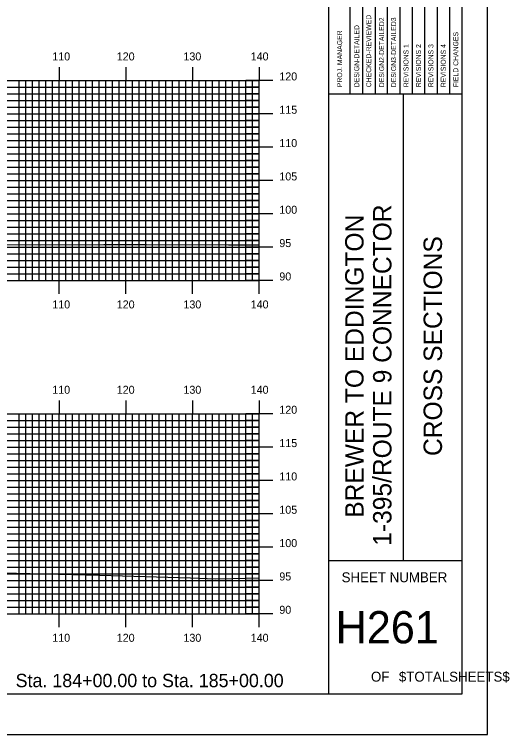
# Model space of a CAD drawing. Extents: x 1786976 to 1787319, y 442591 to 442811.
# Drawn here: x 1787244.9 to 1787319.1, y 442590.5 to 442698.6 of the extents above; entities that cross this region are included whole.
import ezdxf

# ---------------------------------------------------------------- set-up
doc = ezdxf.new("R2010")
doc.units = 0
for name, color, linetype in [('BORDER', 7, 'Continuous'), ('H_V ANNOTATION', 7, 'Continuous'), ('MAJOR', 7, 'Continuous'), ('MINOR', 7, 'Continuous'), ('PLOT BOUNDARY', 7, 'Continuous'), ('S_Roadway_Centerline', 7, 'Continuous')]:
    doc.layers.add(name, color=color, linetype=linetype)

msp = doc.modelspace()

# ---------------------------------------------------------------- linework, layer by layer
at = {"layer": 'BORDER'}
for p, q in [((1787291.99, 442596.67), (1787291.99, 442806.67)), ((1787291.99, 442686.67), (1787311.99, 442686.67)), ((1787303.17, 442616.67), (1787303.17, 442686.67)), ((1787291.99, 442616.67), (1787311.99, 442616.67))]:
    msp.add_line(p, q, dxfattribs=at)
msp.add_lwpolyline([(1786991.99, 442596.67), (1787311.99, 442596.67), (1787311.99, 442806.67), (1786991.99, 442806.67)], close=True, dxfattribs=at)
for points in [[(1787297.09, 442686.68), (1787297.09, 442721.67)], [(1787298.95, 442721.67), (1787298.95, 442686.68)], [(1787300.81, 442686.68), (1787300.81, 442721.67)], [(1787302.68, 442686.68), (1787302.68, 442721.67)], [(1787304.54, 442686.68), (1787304.54, 442721.67)], [(1787306.4, 442686.68), (1787306.4, 442721.67)], [(1787308.27, 442686.68), (1787308.27, 442721.67)], [(1787310.13, 442686.68), (1787310.13, 442721.67)], [(1787295.22, 442686.68), (1787295.22, 442720.26)]]:
    msp.add_lwpolyline(points, dxfattribs=at)
at = {"layer": 'MAJOR'}
for p, q in [((1787251.59, 442690.67), (1787251.59, 442688.67)), ((1787261.59, 442690.67), (1787261.59, 442688.67)), ((1787271.59, 442690.67), (1787271.59, 442688.67)), ((1787281.59, 442690.67), (1787281.59, 442688.67)), ((1787001.59, 442688.67), (1787281.59, 442688.67)), ((1787001.59, 442688.67), (1787281.59, 442688.67)), ((1787251.59, 442658.67), (1787251.59, 442688.67)), ((1787261.59, 442658.67), (1787261.59, 442688.67)), ((1787271.59, 442658.67), (1787271.59, 442688.67)), ((1787283.6, 442688.67), (1787279.59, 442688.67)), ((1787281.59, 442658.67), (1787281.59, 442688.67)), ((1787281.59, 442658.67), (1787281.59, 442688.67)), ((1787001.59, 442683.67), (1787281.59, 442683.67)), ((1787283.6, 442683.67), (1787279.59, 442683.67)), ((1787001.59, 442678.67), (1787281.59, 442678.67)), ((1787283.6, 442678.67), (1787279.59, 442678.67)), ((1787001.59, 442673.67), (1787281.59, 442673.67)), ((1787283.6, 442673.67), (1787279.59, 442673.67)), ((1787001.59, 442668.67), (1787281.59, 442668.67)), ((1787283.6, 442668.67), (1787279.59, 442668.67)), ((1787001.59, 442663.67), (1787281.59, 442663.67)), ((1787283.6, 442663.67), (1787279.59, 442663.67)), ((1787001.59, 442658.67), (1787281.59, 442658.67)), ((1787001.59, 442658.67), (1787281.59, 442658.67)), ((1787251.59, 442656.66), (1787251.59, 442658.67)), ((1787261.59, 442656.66), (1787261.59, 442658.67)), ((1787271.59, 442656.66), (1787271.59, 442658.67)), ((1787283.6, 442658.67), (1787279.59, 442658.67)), ((1787281.59, 442656.66), (1787281.59, 442658.67)), ((1787251.59, 442640.67), (1787251.59, 442638.67)), ((1787261.59, 442640.67), (1787261.59, 442638.67)), ((1787271.59, 442640.67), (1787271.59, 442638.67)), ((1787281.59, 442640.67), (1787281.59, 442638.67)), ((1787001.59, 442638.67), (1787281.59, 442638.67)), ((1787001.59, 442638.67), (1787281.59, 442638.67)), ((1787251.59, 442608.67), (1787251.59, 442638.67)), ((1787261.59, 442608.67), (1787261.59, 442638.67)), ((1787271.59, 442608.67), (1787271.59, 442638.67)), ((1787283.6, 442638.67), (1787279.59, 442638.67)), ((1787281.59, 442608.67), (1787281.59, 442638.67)), ((1787281.59, 442608.67), (1787281.59, 442638.67)), ((1787001.59, 442633.67), (1787281.59, 442633.67)), ((1787283.6, 442633.67), (1787279.59, 442633.67)), ((1787001.59, 442628.67), (1787281.59, 442628.67)), ((1787283.6, 442628.67), (1787279.59, 442628.67)), ((1787001.59, 442623.67), (1787281.59, 442623.67)), ((1787283.6, 442623.67), (1787279.59, 442623.67)), ((1787001.59, 442618.67), (1787281.59, 442618.67)), ((1787283.6, 442618.67), (1787279.59, 442618.67)), ((1787001.59, 442613.67), (1787281.59, 442613.67)), ((1787283.6, 442613.67), (1787279.59, 442613.67)), ((1787001.59, 442608.67), (1787281.59, 442608.67)), ((1787001.59, 442608.67), (1787281.59, 442608.67)), ((1787251.59, 442606.66), (1787251.59, 442608.67)), ((1787261.59, 442606.66), (1787261.59, 442608.67)), ((1787271.59, 442606.66), (1787271.59, 442608.67)), ((1787283.6, 442608.67), (1787279.59, 442608.67)), ((1787281.59, 442606.66), (1787281.59, 442608.67))]:
    msp.add_line(p, q, dxfattribs=at)
at = {"layer": 'MINOR'}
for p, q in [((1787245.59, 442658.67), (1787245.59, 442688.67)), ((1787246.59, 442658.67), (1787246.59, 442688.67)), ((1787247.59, 442658.67), (1787247.59, 442688.67)), ((1787248.59, 442658.67), (1787248.59, 442688.67)), ((1787249.59, 442658.67), (1787249.59, 442688.67)), ((1787250.59, 442658.67), (1787250.59, 442688.67)), ((1787252.59, 442658.67), (1787252.59, 442688.67)), ((1787253.59, 442658.67), (1787253.59, 442688.67)), ((1787254.59, 442658.67), (1787254.59, 442688.67)), ((1787255.59, 442658.67), (1787255.59, 442688.67)), ((1787256.59, 442658.67), (1787256.59, 442688.67)), ((1787257.59, 442658.67), (1787257.59, 442688.67)), ((1787258.59, 442658.67), (1787258.59, 442688.67)), ((1787259.59, 442658.67), (1787259.59, 442688.67)), ((1787260.59, 442658.67), (1787260.59, 442688.67)), ((1787262.59, 442658.67), (1787262.59, 442688.67)), ((1787263.59, 442658.67), (1787263.59, 442688.67)), ((1787264.59, 442658.67), (1787264.59, 442688.67)), ((1787265.59, 442658.67), (1787265.59, 442688.67)), ((1787266.59, 442658.67), (1787266.59, 442688.67)), ((1787267.59, 442658.67), (1787267.59, 442688.67)), ((1787268.59, 442658.67), (1787268.59, 442688.67)), ((1787269.59, 442658.67), (1787269.59, 442688.67)), ((1787270.59, 442658.67), (1787270.59, 442688.67)), ((1787272.59, 442658.67), (1787272.59, 442688.67)), ((1787273.59, 442658.67), (1787273.59, 442688.67)), ((1787274.59, 442658.67), (1787274.59, 442688.67)), ((1787275.59, 442658.67), (1787275.59, 442688.67)), ((1787276.59, 442658.67), (1787276.59, 442688.67)), ((1787277.59, 442658.67), (1787277.59, 442688.67)), ((1787278.59, 442658.67), (1787278.59, 442688.67)), ((1787279.59, 442658.67), (1787279.59, 442688.67)), ((1787280.59, 442658.67), (1787280.59, 442688.67)), ((1787001.59, 442687.67), (1787281.59, 442687.67)), ((1787281.59, 442687.67), (1787279.59, 442687.67)), ((1787001.59, 442686.67), (1787281.59, 442686.67)), ((1787281.59, 442686.67), (1787279.59, 442686.67)), ((1787001.59, 442685.67), (1787281.59, 442685.67)), ((1787281.59, 442685.67), (1787279.59, 442685.67)), ((1787001.59, 442684.67), (1787281.59, 442684.67)), ((1787281.59, 442684.67), (1787279.59, 442684.67)), ((1787001.59, 442682.67), (1787281.59, 442682.67)), ((1787281.59, 442682.67), (1787279.59, 442682.67)), ((1787001.59, 442681.67), (1787281.59, 442681.67)), ((1787001.59, 442680.67), (1787281.59, 442680.67)), ((1787281.59, 442681.67), (1787279.59, 442681.67)), ((1787281.59, 442680.67), (1787279.59, 442680.67)), ((1787001.59, 442679.67), (1787281.59, 442679.67)), ((1787281.59, 442679.67), (1787279.59, 442679.67)), ((1787001.59, 442677.67), (1787281.59, 442677.67)), ((1787281.59, 442677.67), (1787279.59, 442677.67)), ((1787001.59, 442676.67), (1787281.59, 442676.67)), ((1787281.59, 442676.67), (1787279.59, 442676.67)), ((1787001.59, 442675.67), (1787281.59, 442675.67)), ((1787281.59, 442675.67), (1787279.59, 442675.67)), ((1787001.59, 442674.67), (1787281.59, 442674.67)), ((1787281.59, 442674.67), (1787279.59, 442674.67)), ((1787001.59, 442672.67), (1787281.59, 442672.67)), ((1787281.59, 442672.67), (1787279.59, 442672.67)), ((1787001.59, 442671.67), (1787281.59, 442671.67)), ((1787281.59, 442671.67), (1787279.59, 442671.67)), ((1787001.59, 442670.67), (1787281.59, 442670.67)), ((1787281.59, 442670.67), (1787279.59, 442670.67)), ((1787001.59, 442669.67), (1787281.59, 442669.67)), ((1787281.59, 442669.67), (1787279.59, 442669.67)), ((1787001.59, 442667.67), (1787281.59, 442667.67)), ((1787281.59, 442667.67), (1787279.59, 442667.67)), ((1787001.59, 442666.67), (1787281.59, 442666.67)), ((1787281.59, 442666.67), (1787279.59, 442666.67)), ((1787001.59, 442665.67), (1787281.59, 442665.67)), ((1787281.59, 442665.67), (1787279.59, 442665.67)), ((1787001.59, 442664.67), (1787281.59, 442664.67)), ((1787281.59, 442664.67), (1787279.59, 442664.67)), ((1787001.59, 442662.67), (1787281.59, 442662.67)), ((1787281.59, 442662.67), (1787279.59, 442662.67)), ((1787001.59, 442661.67), (1787281.59, 442661.67)), ((1787281.59, 442661.67), (1787279.59, 442661.67)), ((1787001.59, 442660.67), (1787281.59, 442660.67)), ((1787281.59, 442660.67), (1787279.59, 442660.67)), ((1787001.59, 442659.67), (1787281.59, 442659.67)), ((1787281.59, 442659.67), (1787279.59, 442659.67)), ((1787245.59, 442608.67), (1787245.59, 442638.67)), ((1787246.59, 442608.67), (1787246.59, 442638.67)), ((1787247.59, 442608.67), (1787247.59, 442638.67)), ((1787248.59, 442608.67), (1787248.59, 442638.67)), ((1787249.59, 442608.67), (1787249.59, 442638.67)), ((1787250.59, 442608.67), (1787250.59, 442638.67)), ((1787252.59, 442608.67), (1787252.59, 442638.67)), ((1787253.59, 442608.67), (1787253.59, 442638.67)), ((1787254.59, 442608.67), (1787254.59, 442638.67)), ((1787255.59, 442608.67), (1787255.59, 442638.67)), ((1787256.59, 442608.67), (1787256.59, 442638.67)), ((1787257.59, 442608.67), (1787257.59, 442638.67)), ((1787258.59, 442608.67), (1787258.59, 442638.67)), ((1787259.59, 442608.67), (1787259.59, 442638.67)), ((1787260.59, 442608.67), (1787260.59, 442638.67)), ((1787262.59, 442608.67), (1787262.59, 442638.67)), ((1787263.59, 442608.67), (1787263.59, 442638.67)), ((1787264.59, 442608.67), (1787264.59, 442638.67)), ((1787265.59, 442608.67), (1787265.59, 442638.67)), ((1787266.59, 442608.67), (1787266.59, 442638.67)), ((1787267.59, 442608.67), (1787267.59, 442638.67)), ((1787268.59, 442608.67), (1787268.59, 442638.67)), ((1787269.59, 442608.67), (1787269.59, 442638.67)), ((1787270.59, 442608.67), (1787270.59, 442638.67)), ((1787272.59, 442608.67), (1787272.59, 442638.67)), ((1787273.59, 442608.67), (1787273.59, 442638.67)), ((1787274.59, 442608.67), (1787274.59, 442638.67)), ((1787275.59, 442608.67), (1787275.59, 442638.67)), ((1787276.59, 442608.67), (1787276.59, 442638.67)), ((1787277.59, 442608.67), (1787277.59, 442638.67)), ((1787278.59, 442608.67), (1787278.59, 442638.67)), ((1787279.59, 442608.67), (1787279.59, 442638.67)), ((1787280.59, 442608.67), (1787280.59, 442638.67)), ((1787001.59, 442637.67), (1787281.59, 442637.67)), ((1787281.59, 442637.67), (1787279.59, 442637.67)), ((1787001.59, 442636.67), (1787281.59, 442636.67)), ((1787281.59, 442636.67), (1787279.59, 442636.67)), ((1787001.59, 442635.67), (1787281.59, 442635.67)), ((1787281.59, 442635.67), (1787279.59, 442635.67)), ((1787001.59, 442634.67), (1787281.59, 442634.67)), ((1787281.59, 442634.67), (1787279.59, 442634.67)), ((1787001.59, 442632.67), (1787281.59, 442632.67)), ((1787281.59, 442632.67), (1787279.59, 442632.67)), ((1787001.59, 442631.67), (1787281.59, 442631.67)), ((1787281.59, 442631.67), (1787279.59, 442631.67)), ((1787001.59, 442630.67), (1787281.59, 442630.67)), ((1787281.59, 442630.67), (1787279.59, 442630.67)), ((1787001.59, 442629.67), (1787281.59, 442629.67)), ((1787281.59, 442629.67), (1787279.59, 442629.67)), ((1787001.59, 442627.67), (1787281.59, 442627.67)), ((1787281.59, 442627.67), (1787279.59, 442627.67)), ((1787001.59, 442626.67), (1787281.59, 442626.67)), ((1787281.59, 442626.67), (1787279.59, 442626.67)), ((1787001.59, 442625.67), (1787281.59, 442625.67)), ((1787281.59, 442625.67), (1787279.59, 442625.67)), ((1787001.59, 442624.67), (1787281.59, 442624.67)), ((1787281.59, 442624.67), (1787279.59, 442624.67)), ((1787001.59, 442622.67), (1787281.59, 442622.67)), ((1787281.59, 442622.67), (1787279.59, 442622.67)), ((1787001.59, 442621.67), (1787281.59, 442621.67)), ((1787281.59, 442621.67), (1787279.59, 442621.67)), ((1787001.59, 442620.67), (1787281.59, 442620.67)), ((1787281.59, 442620.67), (1787279.59, 442620.67)), ((1787001.59, 442619.67), (1787281.59, 442619.67)), ((1787281.59, 442619.67), (1787279.59, 442619.67)), ((1787001.59, 442617.67), (1787281.59, 442617.67)), ((1787281.59, 442617.67), (1787279.59, 442617.67)), ((1787001.59, 442616.67), (1787281.59, 442616.67)), ((1787281.59, 442616.67), (1787279.59, 442616.67)), ((1787001.59, 442615.67), (1787281.59, 442615.67)), ((1787281.59, 442615.67), (1787279.59, 442615.67)), ((1787001.59, 442614.67), (1787281.59, 442614.67)), ((1787281.59, 442614.67), (1787279.59, 442614.67)), ((1787001.59, 442612.67), (1787281.59, 442612.67)), ((1787281.59, 442612.67), (1787279.59, 442612.67)), ((1787001.59, 442611.67), (1787281.59, 442611.67)), ((1787281.59, 442611.67), (1787279.59, 442611.67)), ((1787001.59, 442610.67), (1787281.59, 442610.67)), ((1787281.59, 442610.67), (1787279.59, 442610.67)), ((1787001.59, 442609.67), (1787281.59, 442609.67)), ((1787281.59, 442609.67), (1787279.59, 442609.67))]:
    msp.add_line(p, q, dxfattribs=at)
at = {"layer": 'PLOT BOUNDARY'}
msp.add_lwpolyline([(1786975.8, 442590.55), (1787315.8, 442590.55), (1787315.8, 442810.55), (1786975.8, 442810.55)], close=True, dxfattribs=at)
at = {"layer": 'S_Roadway_Centerline'}
for points in [[(1787171.93, 442664.67), (1787182.34, 442664.47), (1787200.72, 442664.18), (1787201.57, 442664.17), (1787202.18, 442664.16), (1787211, 442664.25), (1787218.19, 442664.24), (1787222.27, 442664.23), (1787229.46, 442664.14), (1787242.18, 442664.04), (1787248.78, 442664.02), (1787258.29, 442664.07), (1787262.4, 442664.07), (1787264.7, 442664.07), (1787276.96, 442664.02), (1787281.59, 442664)], [(1787177.27, 442614.71), (1787185.92, 442614.82), (1787196.31, 442614.87), (1787197.54, 442614.84), (1787204.65, 442614.76), (1787214.46, 442614.94), (1787217.7, 442614.94), (1787225.22, 442614.93), (1787237.74, 442614.87), (1787243.12, 442614.8), (1787257.71, 442614.46), (1787271.3, 442614.07), (1787275.05, 442613.91), (1787277.58, 442613.95), (1787281.59, 442614.05)]]:
    msp.add_lwpolyline(points, dxfattribs=at)

# ---------------------------------------------------------------- texts
at = {"layer": 'BORDER'}
for s, height, p in [('CHECKED-REVIEWED', 0.7455, (1787298.35, 442687.65)), ('DESIGN2-DETAILED2', 0.7455, (1787300.29, 442687.65)), ('DESIGN3-DETAILED3', 0.7455, (1787302.08, 442687.65)), ('PROJ. MANAGER', 0.7455, (1787294, 442687.65)), ('DESIGN-DETAILED', 0.7455, (1787296.56, 442687.65)), ('FIELD CHANGES', 0.7455, (1787311.4, 442687.65)), ('REVISIONS 1', 0.7455, (1787303.94, 442687.65)), ('REVISIONS 2', 0.7455, (1787305.81, 442687.65)), ('REVISIONS 3', 0.7455, (1787307.67, 442687.65)), ('REVISIONS 4', 0.7455, (1787309.53, 442687.65)), ('1-395/ROUTE 9 CONNECTOR', 2.7557, (1787301.39, 442618.87)), ('BREWER TO EDDINGTON', 2.7557, (1787297.21, 442623.07)), ('CROSS SECTIONS', 2.7557, (1787308.96, 442632.34))]:
    msp.add_text(s, height=height, rotation=90, dxfattribs=at).set_placement(p)
for s, height, p in [('SHEET NUMBER', 1.4905, (1787293.92, 442613.4)), ('H261', 4.839, (1787293.02, 442604.23)), ('OF', 1.491, (1787298.32, 442598.49)), ('$TOTALSHEETS$', 1.4905, (1787302.5, 442598.49))]:
    msp.add_text(s, height=height, dxfattribs=at).set_placement(p)
at = {"layer": 'H_V ANNOTATION'}
for s, height, p in [('110', 1.2, (1787250.57, 442691.67)), ('120', 1.2, (1787260.23, 442691.67)), ('130', 1.2, (1787270.22, 442691.67)), ('140', 1.2, (1787280.3, 442691.67)), ('120', 1.2, (1787284.59, 442688.67)), ('115', 1.2, (1787284.59, 442683.67)), ('110', 1.2, (1787284.59, 442678.67)), ('105', 1.2, (1787284.59, 442673.67)), ('100', 1.2, (1787284.59, 442668.67)), ('95', 1.2, (1787284.59, 442663.67)), ('90', 1.2, (1787284.59, 442658.67)), ('110', 1.2, (1787250.57, 442654.47)), ('120', 1.2, (1787260.23, 442654.47)), ('130', 1.2, (1787270.22, 442654.47)), ('140', 1.2, (1787280.3, 442654.47)), ('110', 1.2, (1787250.57, 442641.67)), ('120', 1.2, (1787260.23, 442641.67)), ('130', 1.2, (1787270.22, 442641.67)), ('140', 1.2, (1787280.3, 442641.67)), ('120', 1.2, (1787284.59, 442638.67)), ('115', 1.2, (1787284.59, 442633.67)), ('110', 1.2, (1787284.59, 442628.67)), ('105', 1.2, (1787284.59, 442623.67)), ('100', 1.2, (1787284.59, 442618.67)), ('95', 1.2, (1787284.59, 442613.67)), ('90', 1.2, (1787284.59, 442608.67)), ('110', 1.2, (1787250.57, 442604.47)), ('120', 1.2, (1787260.23, 442604.47)), ('130', 1.2, (1787270.22, 442604.47)), ('140', 1.2, (1787280.3, 442604.47)), ('Sta. 184+00.00 to Sta. 185+00.00', 2.0004, (1787245.08, 442597.66))]:
    msp.add_text(s, height=height, dxfattribs=at).set_placement(p)

doc.saveas('drawing.dxf')
